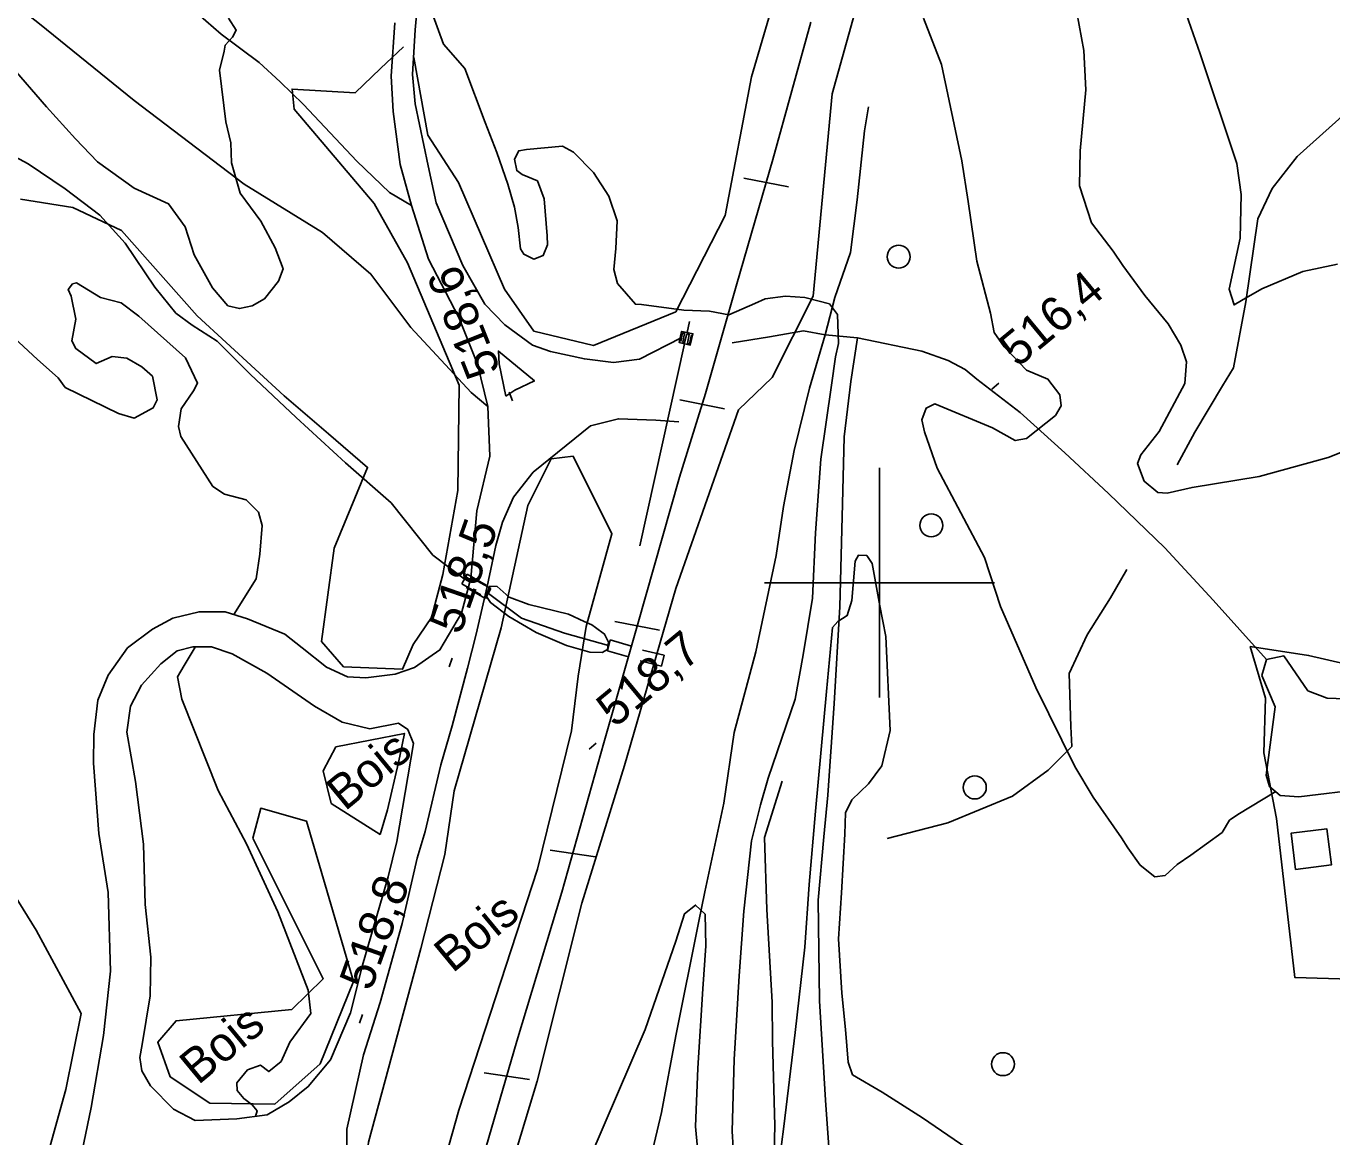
# Model space of a CAD drawing. Extents: x 347059 to 352153, y 6073752 to 6078601.
# Drawn here: x 347588.7 to 347759, y 6075527.7 to 6075672.7 of the extents above; entities that cross this region are included whole.
import ezdxf

# ---------------------------------------------------------------- set-up
doc = ezdxf.new("R2010")
doc.units = 0
for name, color, linetype in [('Level 1', 7, 'Continuous'), ('Level 19', 7, 'Continuous'), ('Level 2', 7, 'Continuous'), ('Level 22', 7, 'Continuous'), ('Level 23', 7, 'Continuous'), ('Level 26', 7, 'Continuous'), ('Level 3', 7, 'Continuous'), ('Level 31', 7, 'Continuous'), ('Level 36', 7, 'Continuous'), ('Level 4', 7, 'Continuous'), ('Level 44', 7, 'Continuous'), ('Level 61', 7, 'Continuous')]:
    doc.layers.add(name, color=color, linetype=linetype)

msp = doc.modelspace()

# ---------------------------------------------------------------- linework, layer by layer
at = {"layer": 'Level 1'}
for points in [[(347621.59, 6075639.38), (347619.79, 6075637.08), (347618.18, 6075636.14), (347616.52, 6075635.78), (347615, 6075636.13), (347612.98, 6075638.48), (347610.61, 6075642.8), (347609.41, 6075646.47), (347607.27, 6075649.48), (347602.77, 6075651.52), (347597.98, 6075654.96), (347595.1, 6075657.94), (347591.34, 6075662.13), (347586.61, 6075667.6), (347580.78, 6075672.43), (347575.07, 6075675.7)], [(347615.07, 6075673.68), (347616.08, 6075672.14), (347615.62, 6075671.21), (347614.66, 6075670.17), (347614.52, 6075669.39), (347613.92, 6075666.91), (347614.72, 6075660.17), (347615.4, 6075657.43), (347615.46, 6075654.8), (347616.6, 6075650.85), (347619.31, 6075647.2), (347621.17, 6075643.72), (347622.19, 6075640.97), (347621.59, 6075639.38)], [(347598.36, 6075637.22), (347595.24, 6075639.14), (347594.74, 6075639.02), (347594.16, 6075638.29), (347594.54, 6075637.41), (347595.18, 6075634.39), (347594.65, 6075631.59), (347595.14, 6075630.57), (347597.83, 6075628.6), (347599.89, 6075629.55), (347601.83, 6075629.32), (347603.78, 6075628.2), (347605.15, 6075626.96), (347605.78, 6075623.86), (347605.26, 6075622.81), (347602.76, 6075621.49), (347600.73, 6075622.09), (347593.78, 6075625.49), (347592.85, 6075626.74), (347590.17, 6075629.13), (347585.22, 6075633.73)], [(347615.79, 6075595.85), (347618.69, 6075600.5), (347619.16, 6075603.72), (347619.49, 6075607.47), (347618.99, 6075609.2), (347617.37, 6075610.81), (347614.57, 6075611.57), (347613.04, 6075612.58), (347608.85, 6075619.07), (347608.54, 6075620.4), (347608.91, 6075622.69), (347610.51, 6075625.07), (347611.04, 6075626.04), (347609.47, 6075629.37), (347603.36, 6075634.81), (347601.09, 6075636.54), (347598.36, 6075637.22)], [(347616.15, 6075534.73), (347617.57, 6075536.43), (347619.25, 6075537.02), (347620.35, 6075536.19), (347621.95, 6075537.51), (347623.08, 6075540.05), (347625.8, 6075543.77), (347625.8, 6075543.77), (347625.49, 6075546.84), (347621.51, 6075557.06), (347617.43, 6075565.91), (347613.75, 6075572.89), (347609, 6075584.79), (347608.44, 6075587.72), (347609.28, 6075589.21), (347610.71, 6075591.58), (347610.77, 6075591.63)], [(347652.33, 6075499.3), (347654.48, 6075504.82), (347657.14, 6075513.31), (347662.23, 6075524.88), (347669.46, 6075541.69), (347673.43, 6075553.21), (347674.57, 6075556.8), (347676.01, 6075557.93), (347677.25, 6075556.76), (347677.37, 6075552.62), (347676.98, 6075547), (347676.29, 6075536.62), (347676, 6075529.02), (347676.85, 6075520.07), (347677.13, 6075512.28), (347677.18, 6075507.36), (347677.42, 6075500.6), (347676.99, 6075490.74), (347676.94, 6075486.27)], [(347618.61, 6075530.33), (347618.83, 6075531.08), (347618.16, 6075531.84), (347617.06, 6075532.67), (347616.2, 6075533.7), (347616.15, 6075534.73)]]:
    msp.add_lwpolyline(points, dxfattribs=at)
at = {"layer": 'Level 19'}
for points in [[(347640.23, 6075680.73), (347639.42, 6075672.19), (347639.1, 6075666.33), (347639.42, 6075662.53), (347641.11, 6075654.4), (347642.16, 6075649.57), (347645.64, 6075641.39), (347648.5, 6075636.38), (347651.14, 6075633.66), (347654.75, 6075631.03), (347657.08, 6075630.17), (347661.51, 6075629.22), (347665.29, 6075628.77), (347668.69, 6075629.2), (347674.14, 6075631.99)], [(347595.49, 6075523.54), (347597.17, 6075531.51), (347598.75, 6075540.9), (347599.68, 6075549.28), (347599.37, 6075559.55), (347598.15, 6075567.28), (347597.47, 6075576.47), (347597.5, 6075580.21), (347598.03, 6075584.68), (347599.36, 6075587.95), (347601.9, 6075591.5), (347605.17, 6075593.94), (347607.8, 6075595.37), (347611.23, 6075596.21), (347614.65, 6075596.2), (347617.56, 6075595.29), (347622.41, 6075593.27), (347624.69, 6075591.51), (347627.85, 6075589), (347630.61, 6075587.73), (347633, 6075587.59), (347636.82, 6075588.08), (347639.33, 6075588.95), (347642.67, 6075591.23), (347645.48, 6075596.05), (347646.71, 6075600.59), (347647.46, 6075609.39), (347649.18, 6075616.53), (347648.91, 6075623.01), (347647.58, 6075628.51), (347645.12, 6075634.62), (347641.16, 6075642.23), (347638.97, 6075649.26), (347637.47, 6075654.61), (347636.54, 6075661.5), (347636.32, 6075666.14), (347636.77, 6075673.09)], [(347651.28, 6075624.35), (347650.38, 6075628.56), (347650.3, 6075630.23), (347655, 6075626.34), (347652.43, 6075625.12), (347651.28, 6075624.35)], [(347673.83, 6075621.01), (347670.84, 6075621.24), (347665.94, 6075621.41), (347662.3, 6075620.47), (347654.82, 6075614.42), (347652.26, 6075611.16), (347650.83, 6075607.9), (347649.96, 6075604.88), (347648.82, 6075599.52), (347647.37, 6075593.3), (347646.26, 6075588.87), (347644.28, 6075581.33), (347642.77, 6075576.23), (347640.72, 6075567.55), (347639.71, 6075564.04), (347637.75, 6075555.52), (347634.88, 6075545.23), (347632.67, 6075538.39), (347630.5, 6075528.69), (347630.54, 6075524.17)], [(347603.82, 6075539.72), (347604.85, 6075546.06), (347604.93, 6075551.14), (347604.21, 6075558.02), (347604.01, 6075565.88), (347602.94, 6075574.04), (347601.82, 6075580.51), (347602.31, 6075583.89), (347603.73, 6075586.62), (347606.25, 6075589.4), (347608.36, 6075591.13), (347610.43, 6075591.63), (347612.84, 6075591.65), (347615.54, 6075590.72), (347620.08, 6075588.18), (347626.28, 6075583.89), (347629.92, 6075581.79), (347633.52, 6075580.95), (347637.24, 6075581.65), (347638.48, 6075580.83), (347639.21, 6075579.02), (347637.06, 6075566.24), (347635.91, 6075561.6), (347632.58, 6075550.08), (347630.99, 6075543.85), (347628.39, 6075537.73), (347625.49, 6075534.24), (347622.98, 6075532.23), (347620.13, 6075530.53), (347616.18, 6075530.01), (347610.75, 6075529.8), (347607.89, 6075531.28), (347604.9, 6075534.31), (347603.78, 6075536.3), (347603.5, 6075538.03), (347603.82, 6075539.72)], [(347763.39, 6075573.1), (347754.7, 6075572.05), (347752.28, 6075572.24), (347750.9, 6075573.4), (347750.45, 6075574.9), (347751.65, 6075583.8), (347749.89, 6075587.88), (347750.49, 6075590), (347752.76, 6075590.44), (347755.91, 6075585.89), (347758.4, 6075584.93), (347764.31, 6075584.72)]]:
    msp.add_lwpolyline(points, dxfattribs=at)
at = {"layer": 'Level 2'}
for points in [[(347731.78, 6075697.82), (347741.84, 6075669.06), (347746.62, 6075654.73), (347747.19, 6075650.66), (347747.08, 6075644.98), (347745.65, 6075638.32), (347746.26, 6075636.27), (347747.26, 6075636.85), (347749.89, 6075638.36), (347755.23, 6075640.63), (347759.78, 6075641.58)], [(347725.15, 6075677.77), (347726.69, 6075669.46), (347726.93, 6075664.33), (347726.18, 6075656.39), (347726.11, 6075651.8), (347727.69, 6075646.99), (347730.48, 6075643.3), (347731.76, 6075641.43), (347734.61, 6075637.51), (347737.68, 6075633.79), (347739.32, 6075631.01), (347740.06, 6075628.83), (347739.86, 6075626), (347736.5, 6075619.76), (347734.09, 6075616.71), (347733.69, 6075615.58), (347734.56, 6075613.24), (347736.32, 6075611.76), (347737.56, 6075611.71), (347740.79, 6075612.44), (347749.56, 6075613.85), (347758.54, 6075616.35), (347764.92, 6075618.87)], [(347694.27, 6075629.51), (347694.64, 6075631.25), (347694.52, 6075635), (347693.47, 6075636.39), (347690.28, 6075637.22), (347687.75, 6075637.39), (347685.11, 6075637.06), (347683.74, 6075636.46), (347680.35, 6075634.97), (347677.83, 6075635.43), (347674.5, 6075635.6), (347668.97, 6075636.34), (347668.17, 6075636.35), (347665.81, 6075639.04), (347665.34, 6075640.9), (347665.6, 6075643.64), (347665.8, 6075647.25), (347664.72, 6075650.47), (347662.69, 6075653.57), (347660.11, 6075656.21), (347658.66, 6075657), (347653.97, 6075656.57), (347652.94, 6075656.38), (347652.4, 6075655.27), (347652.69, 6075653.79), (347653.37, 6075653.29), (347655.39, 6075652.45), (347656.26, 6075650.11), (347656.67, 6075645.28), (347656.71, 6075644.12), (347656.14, 6075642.72), (347654.93, 6075642.25), (347653.61, 6075642.89), (347653.17, 6075643.58), (347652.86, 6075646.37), (347652.38, 6075649.03), (347651.5, 6075652.02), (347650.08, 6075656.14), (347648.57, 6075660.06), (347645.9, 6075667.14), (347643.15, 6075670.3), (347641.65, 6075674.36)], [(347705.77, 6075673.68), (347708.11, 6075667.64), (347710.77, 6075655.09), (347711.58, 6075649.78), (347712.73, 6075641.96), (347714.49, 6075635.17), (347714.98, 6075632.65), (347716.26, 6075630.78), (347719.18, 6075627.74), (347721.98, 6075626.59), (347723.54, 6075624.55), (347723.69, 6075623.08), (347722.96, 6075621.82), (347719.2, 6075618.84), (347717.72, 6075618.56), (347714.74, 6075620.22), (347707.24, 6075623.34), (347706.1, 6075622.79), (347705.52, 6075621.25), (347705.88, 6075619.69), (347707.54, 6075614.94), (347713.72, 6075603.29), (347715.81, 6075596.9), (347720.42, 6075586.34), (347725.49, 6075576.03), (347727.88, 6075572.02), (347731.6, 6075566.71), (347732.42, 6075565.39)], [(347694.27, 6075629.51), (347693.77, 6075625.78), (347692.35, 6075616.11), (347691.65, 6075606.51), (347691.27, 6075597.97), (347690.06, 6075590.6), (347689.01, 6075584.82), (347685.48, 6075574.48), (347684.49, 6075571.01), (347683.32, 6075566.33), (347682.3, 6075557.12), (347681.71, 6075548.68), (347681.04, 6075537.77), (347680.8, 6075528.42), (347681.56, 6075515.37)], [(347686.63, 6075521.97), (347687.53, 6075529.01), (347689.01, 6075541.29), (347690.29, 6075552.43), (347690.85, 6075560.59), (347691.68, 6075570.18), (347693.1, 6075585.81), (347693.89, 6075594.16), (347694.57, 6075594.96), (347695.79, 6075595.72), (347696.41, 6075597.7), (347696.83, 6075602.82), (347697.26, 6075603.58), (347698.35, 6075603.54), (347699.05, 6075602.53), (347700.05, 6075596.99), (347700.84, 6075592.99), (347701.42, 6075580.72), (347700.32, 6075576.11), (347698.57, 6075573.73), (347696.41, 6075571.68), (347695.59, 6075569.95), (347695.47, 6075567.2), (347695.04, 6075559.53), (347694.68, 6075553.53), (347695.1, 6075546.44), (347695.59, 6075541.67), (347695.92, 6075537.42), (347696.49, 6075535.77), (347700.35, 6075533.51), (347705.63, 6075530.16), (347716.36, 6075522.8)], [(347662.94, 6075594.15), (347664.14, 6075593.29), (347664.67, 6075592.23), (347664.52, 6075591.27), (347663.84, 6075590.91), (347662.22, 6075590.95), (347659.18, 6075591.83), (347655.23, 6075593.51), (347651.67, 6075595.6), (347649.28, 6075597.41), (347648.84, 6075598.09), (347648.74, 6075598.47), (347649.19, 6075599.54), (347650.12, 6075599.51), (347651.69, 6075598.13), (347654.27, 6075597.16), (347659.44, 6075595.92), (347661.49, 6075594.95), (347662.48, 6075594.51), (347662.94, 6075594.15)], [(347732.42, 6075565.39), (347734.03, 6075563.12), (347735.93, 6075561.63), (347737.26, 6075561.79), (347738.86, 6075563.24), (347740.65, 6075564.45), (347744.72, 6075567.41), (347745.68, 6075569), (347746.77, 6075569.77), (347751.7, 6075572.73)]]:
    msp.add_lwpolyline(points, dxfattribs=at)
at = {"layer": 'Level 22'}
for points in [[(347648.91, 6075623.01), (347646.75, 6075624.85), (347638.88, 6075633.32), (347633.65, 6075640.29), (347627.33, 6075645.73), (347617.11, 6075652.02), (347602.78, 6075662.93), (347590.42, 6075672.95), (347580.17, 6075681.03), (347571.73, 6075689.3), (347567.16, 6075695.32), (347562.74, 6075705.39)], [(347610.14, 6075675.1), (347614.13, 6075671.59), (347619.08, 6075667.93), (347621.8, 6075665.37), (347624.86, 6075662.42), (347631.8, 6075655.04), (347636.07, 6075650.94), (347638.97, 6075649.26), (347638.97, 6075649.26)], [(347669.11, 6075520.36), (347671.58, 6075530.83), (347673.44, 6075540.85), (347676.39, 6075555.6), (347677.22, 6075559.64), (347679.72, 6075571.22), (347681.07, 6075580.45), (347683.86, 6075590.99), (347686.52, 6075603.54), (347687.49, 6075609.96), (347688.86, 6075617.25), (347690.86, 6075625.38), (347692.93, 6075632.37), (347694.19, 6075637.23), (347696.22, 6075643.12), (347697.11, 6075650), (347698.07, 6075658.99), (347698.56, 6075662.12)], [(347680.79, 6075631.31), (347685.64, 6075632.08), (347690.08, 6075632.88), (347692.93, 6075632.37), (347697.12, 6075631.98), (347705.55, 6075630.24), (347708.95, 6075629), (347711.17, 6075627.82), (347712.7, 6075626.57), (347718.38, 6075622.23), (347724.2, 6075616.95), (347729.9, 6075611.63), (347737.25, 6075604.56), (347743.56, 6075597.73), (347750.49, 6075590)], [(347704.6, 6075422.45), (347703.58, 6075435.93), (347702.82, 6075450.77), (347700.28, 6075467.42), (347698.63, 6075477.24), (347697.24, 6075486.83), (347695.82, 6075498.06), (347695.74, 6075502.02), (347694.86, 6075506.19), (347694.1, 6075516.55), (347692.97, 6075532.44), (347692.17, 6075545.42), (347691.99, 6075558.55), (347692.74, 6075566.82), (347693.27, 6075572.27), (347694.1, 6075584.23), (347694.82, 6075596.85), (347695.19, 6075610.31), (347695.4, 6075619.03), (347696.28, 6075626.27), (347697.12, 6075631.98)]]:
    msp.add_lwpolyline(points, dxfattribs=at)
at = {"layer": 'Level 23'}
for p, q in [((347682.3, 6075652.8), (347688.14, 6075651.67)), ((347674.59, 6075631.19), (347668.76, 6075604.83)), ((347673.96, 6075623.86), (347679.8, 6075622.72)), ((347665.49, 6075594.94), (347671.33, 6075593.81)), ((347657.03, 6075565.09), (347662.94, 6075564.23)), ((347648.43, 6075536.02), (347654.34, 6075535.16))]:
    msp.add_line(p, q, dxfattribs=at)
for points in [[(347609.23, 6075382.41), (347611.75, 6075395.83), (347614.2, 6075409.25), (347616.07, 6075418.24), (347619.2, 6075431.04), (347622.12, 6075441.98), (347625.66, 6075453.7), (347628.94, 6075464.13), (347632.63, 6075475.13), (347637.59, 6075489.59), (347641.51, 6075503.06), (347647.56, 6075522.49), (347652.71, 6075540.14), (347658.57, 6075559.61), (347664.03, 6075579.1), (347668.39, 6075594.32), (347673.93, 6075613.79), (347677.32, 6075624.7), (347681.41, 6075639.01), (347686.09, 6075655.26), (347691.07, 6075673.19)], [(347675.24, 6075634.12), (347674.93, 6075632.65), (347675.66, 6075632.5), (347675.33, 6075631.03), (347673.86, 6075631.36), (347674.19, 6075632.81), (347674.93, 6075632.65)], [(347675.47, 6075632.35), (347675.24, 6075631.17), (347674.94, 6075631.24), (347675.18, 6075632.41), (347674.88, 6075632.49), (347674.59, 6075631.35), (347674.37, 6075631.39), (347674.59, 6075632.55), (347674.33, 6075632.61), (347674.09, 6075631.49)]]:
    msp.add_lwpolyline(points, dxfattribs=at)
at = {"layer": 'Level 26'}
for p, q in [((347646.23, 6075601.12), (347645.5, 6075599.85)), ((347646.23, 6075601.12), (347648.71, 6075599.68)), ((347645.5, 6075599.85), (347648.01, 6075598.42)), ((347648.59, 6075597.93), (347646.09, 6075599.37)), ((347649.31, 6075599.23), (347646.79, 6075600.63)), ((347648.59, 6075597.93), (347649.31, 6075599.23)), ((347664.89, 6075592.54), (347664.51, 6075591.11)), ((347664.89, 6075592.54), (347667.67, 6075591.73)), ((347664.51, 6075591.11), (347667.28, 6075590.33)), ((347671.91, 6075590.55), (347669.11, 6075591.21)), ((347671.59, 6075589.12), (347671.91, 6075590.55)), ((347671.59, 6075589.12), (347668.78, 6075589.79))]:
    msp.add_line(p, q, dxfattribs=at)
at = {"layer": 'Level 3'}
for p, q in [((347652.15, 6075623.74), (347651.71, 6075624.86)), ((347714.67, 6075625.28), (347715.59, 6075626.05)), ((347643.86, 6075589.01), (347644.26, 6075590.15)), ((347662.12, 6075578.27), (347663.04, 6075579.04)), ((347632.15, 6075542.52), (347632.55, 6075543.64))]:
    msp.add_line(p, q, dxfattribs=at)
at = {"layer": 'Level 31'}
msp.add_lwpolyline([(347754.29, 6075562.58), (347753.71, 6075567.3), (347758.39, 6075567.87), (347758.97, 6075563.16), (347754.29, 6075562.58)], dxfattribs=at)
at = {"layer": 'Level 36'}
for centre in [(347702.51, 6075642.56), (347706.77, 6075607.49), (347712.44, 6075573.28), (347716.12, 6075537.16)]:
    msp.add_circle(centre, 1.5, dxfattribs=at)
at = {"layer": 'Level 4'}
for points in [[(347738.83, 6075615.39), (347741.15, 6075619.65), (347744.74, 6075625.7), (347746.18, 6075628.07), (347747.81, 6075636.67), (347749.37, 6075647.49), (347751.26, 6075651.47), (347754.51, 6075655.63), (347760.77, 6075661.24), (347765.36, 6075668.52), (347767.31, 6075674.38), (347771.14, 6075683.89), (347775.48, 6075690.51), (347779.72, 6075694.91)], [(347564.85, 6075674.94), (347570.04, 6075671.13), (347575.09, 6075667.83), (347577.91, 6075663.95), (347579.61, 6075660.49), (347581.63, 6075658.59), (347588.95, 6075654.66), (347593.77, 6075651.41), (347598.3, 6075647.98), (347601.59, 6075644.32), (347605.46, 6075638.58), (347608.21, 6075635.2), (347610.32, 6075633.62), (347613.61, 6075631.54), (347617.91, 6075627.23), (347623.9, 6075621.58), (347630.35, 6075615.64), (347636.32, 6075610.43), (347641.73, 6075603.6), (347645.83, 6075600.49)], [(347700.99, 6075566.6), (347708.91, 6075568.64), (347717.38, 6075572.14), (347722.02, 6075575.53), (347725.1, 6075578.63), (347724.97, 6075581.24), (347724.77, 6075588.17), (347727.1, 6075593.2), (347730.15, 6075598.02), (347732.26, 6075601.72)], [(347648.98, 6075598.58), (347653.32, 6075595.37), (347658.9, 6075593.44), (347664.67, 6075591.82)], [(347685.95, 6075514.17), (347686.36, 6075529.1), (347686.03, 6075540.21), (347686.01, 6075545.26), (347685.3, 6075557.34), (347685, 6075566.76), (347687.3, 6075574.1)]]:
    msp.add_lwpolyline(points, dxfattribs=at)
at = {"layer": 'Level 44'}
for points in [[(347700.98, 6075731.95), (347700.39, 6075721.02), (347695.17, 6075704.61), (347688.04, 6075682.24), (347683.32, 6075666.02), (347679.89, 6075647.95), (347673.42, 6075635.35), (347662.7, 6075630.97), (347654.9, 6075632.86), (347651.1, 6075638.34), (347645.07, 6075652.24), (347641.1, 6075658.43), (347639.25, 6075668.58)], [(347647.52, 6075509.06), (347655.34, 6075534.94), (347661.18, 6075558.19), (347666.74, 6075576.15), (347673.44, 6075599.27), (347681.62, 6075622.58), (347686, 6075626.79), (347691.34, 6075637.42), (347693.84, 6075663.83), (347701.08, 6075689.87)], [(347637.93, 6075669.97), (347634.93, 6075667.11), (347631.61, 6075663.96), (347623.37, 6075664.43), (347623.66, 6075661.81), (347634.07, 6075649.49), (347638.42, 6075641.78), (347645.17, 6075625.79), (347645, 6075612.05), (347643.02, 6075601.06), (347641.55, 6075595.48), (347639.16, 6075591.95), (347637.8, 6075588.71), (347630.09, 6075589.04), (347627.23, 6075592.35)], [(347627.23, 6075592.35), (347628.85, 6075604.51), (347633.22, 6075615.05), (347628.12, 6075619.42), (347622.33, 6075624.4), (347610.97, 6075634.84), (347601.11, 6075645.98), (347594.77, 6075648.98), (347587.94, 6075650.06)], [(347659.83, 6075580.65), (347655.4, 6075562.61), (347645.14, 6075531.14), (347640.41, 6075514.32), (347634.25, 6075512.5), (347632.16, 6075517.04), (347633.33, 6075526.97), (347640.17, 6075552.26), (347643.3, 6075564.51), (347644.52, 6075572.84), (347650.63, 6075594.11), (347654.11, 6075610.07), (347657.18, 6075616.16), (347660.04, 6075616.51), (347665.11, 6075606.38), (347661.76, 6075594.3), (347660.7, 6075587.81), (347659.83, 6075580.65)], [(347760.72, 6075589.43), (347756, 6075590.52), (347748.37, 6075591.67), (347750.38, 6075584.93), (347750.17, 6075577.8), (347751.79, 6075569.22), (347754.2, 6075548.47), (347761.49, 6075548.24)], [(347634.87, 6075567.14), (347628.49, 6075571.2), (347627.41, 6075575.43), (347629.1, 6075578.56), (347638.03, 6075580.34), (347637.27, 6075576.52), (347635.83, 6075570.34), (347634.87, 6075567.14)], [(347607.47, 6075535.5), (347605.85, 6075540.01), (347608.25, 6075542.83), (347623.32, 6075544.31), (347627.43, 6075548.31), (347618.26, 6075566.65), (347619.28, 6075570.56), (347625.27, 6075568.89), (347631.4, 6075547.93), (347627.04, 6075537.19), (347621.12, 6075531.93), (347612.66, 6075532.07), (347607.47, 6075535.5)], [(347582.93, 6075565.96), (347589.99, 6075554.63), (347595.87, 6075543.79), (347593.87, 6075533.84), (347586.4, 6075507.09)]]:
    msp.add_lwpolyline(points, dxfattribs=at)
at = {"layer": 'Level 61'}
for p, q in [((347700, 6075585), (347700, 6075615)), ((347685, 6075600), (347715, 6075600))]:
    msp.add_line(p, q, dxfattribs=at)

# ---------------------------------------------------------------- texts
at = {"layer": 'Level 3'}
for s, rotation, p in [('518,6', 111.6336, (347650.61, 6075627.78)), ('516,4', 39.62, (347718.03, 6075628)), ('518,5', 70.7938, (347645.34, 6075593.08)), ('518,7', 39.62, (347665.48, 6075580.98)), ('518,8', 70.2448, (347633.66, 6075546.56))]:
    msp.add_text(s, height=4.5, rotation=rotation, dxfattribs=at).set_placement(p)
at = {"layer": 'Level 44'}
for p in [(347630.27, 6075570.1), (347644.31, 6075548.96), (347611.11, 6075534.36)]:
    msp.add_text('Bois', height=4.5, rotation=39.568, dxfattribs=at).set_placement(p)

doc.saveas('drawing.dxf')
